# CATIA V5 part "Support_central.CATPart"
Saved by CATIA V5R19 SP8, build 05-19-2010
Part number: Support_central
Bounding box of the stored display mesh (mm): x -4 to 53, y -100 to 100, z -93 to 93
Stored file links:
  G:\EU_thinkMotion\CFAO_2010\SIL_groupe2\SIL_groupe2\msauret\Brevet_Sauret_parametre\Support_central.CATPart
  F:\Brevet_Sauret paramétré\Product3.CATProduct
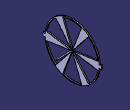
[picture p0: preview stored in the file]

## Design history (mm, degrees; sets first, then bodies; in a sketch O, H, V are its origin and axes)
Set1
  Plane1: linked copy from another document
  Plane2: linked copy from another document
  Line1: linked copy from another document
  Plane3: linked copy from another document
  Plane4: linked copy from another document
Body1 (main body)
  Sketch1 on Plane1, origin (0, 0, 0), H (0, 1, 0), V (0, 0, 1)
    arc A1 centre (0, 0) radius 93 from (92.9353, 3.4677) to (-92.9353, 3.4677) ccw
    line L1 (92.9353, 3.4677) -> (100, 7)
    point P1 (100, 7)
    line L2 (100, 7) -> (100, -7)
    point P2 (100, -7)
    line L3 (100, -7) -> (92.9353, -3.4677)
    point P3 (92.9353, 3.4677)
    point P4 (92.9353, -3.4677)
    point P5 (-100, 7)
    point P6 (-92.9353, 3.4677)
    line L4 (-92.9353, 3.4677) -> (-100, 7)
    point P7 (-100, -7)
    line L5 (-100, 7) -> (-100, -7)
    point P8 (-92.9353, -3.4677)
    line L6 (-100, -7) -> (-92.9353, -3.4677)
    arc A2 centre (0, 0) radius 93 from (-92.9353, -3.4677) to (92.9353, -3.4677) ccw
    vertical: L2 V
    symmetry: P1 P5 V, P3 P6 V, L1 L4 V, P2 P7 V, L2 L5 V, P4 P8 V, L3 L6 V
    coincidence: A1 A2
  Pad1: profile Sketch1, direction (1, 0, 0), up to Plane2
  Sketch2 on Plane1, origin (0, 0, 0), H (0, 1, 0), V (0, 0, 1)
    arc A1 centre (0, 0) radius 90 from (32.6202, 83.8804) to (-32.6202, 83.8804) ccw
    line L1 (32.6202, 83.8804) -> (2.1747, 5.592)
    line L2 (-2.1747, 5.592) -> (-32.6202, 83.8804)
    arc A2 centre (0, 0) radius 6 from (2.1747, 5.592) to (-2.1747, 5.592) ccw
    point P3 (0, 0)
    coincidence: P3 H
  Pocket1: profile Sketch2, direction (-1, 0, 0), up to Plane2
  CircPattern1: of Pocket1, instances 6, angular step 60, axis from Line1
  Sketch3 on Plane1, origin (0, 0, 0), H (0, 1, 0), V (0, 0, 1)
    circle A1 centre (0, 0) radius 4
  Pad2: profile Sketch3, direction (1, 0, 0), up to Plane3
  Sketch4 on Plane3, origin (2, 0, 0), H (0, 1, 0), V (0, 0, 1)
    circle A1 centre (0, 0) radius 2
  Pad3: profile Sketch4, direction (1, 0, 0), up to Plane4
